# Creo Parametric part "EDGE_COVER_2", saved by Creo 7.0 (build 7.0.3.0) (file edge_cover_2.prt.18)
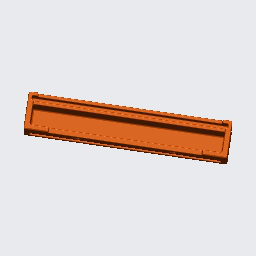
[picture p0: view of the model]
Units: millimeter Kilogram Sec (mmKs); MM, KILOGRAM, SECS

Created from: EDGE_COVER_1.PRT

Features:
  1. coordinate system
  2. datum plane "RIGHT"
  3. datum plane "TOP"
  4. datum plane "FRONT"
  5. protrusion
  6. cut
  7. protrusion
  8. protrusion
  9. extruded cut "Extrude 5"
  10. extruded cut "Extrude 6"
  11. extrusion "Extrude 7"
  12. extrusion "Extrude 8"
  13. extrusion "Extrude 9"
  14. chamfer "Chamfer 1"
  15. extruded cut "Extrude 10"
  16. round "Round 1"
  17. round "Round 2"
  18. round "Round 3"
  19. round "Round 4"
  20. round "Round 5"
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
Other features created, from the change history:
  round "Round 1" (2 times)
  round "Round 2" (2 times)
  round "Round 3" (2 times)
  chamfer "Chamfer 1"
  extruded cut "Extrude 6"
  round "Round 4"
  extruded cut "Extrude 10"
  round "Round 6"
  round "Round 7"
